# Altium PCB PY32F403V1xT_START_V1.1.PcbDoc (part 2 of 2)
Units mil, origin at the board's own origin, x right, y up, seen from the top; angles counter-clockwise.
Board outline 1771.65 x 2660.63 mil, 2 copper layers (Top Layer, Bottom Layer); 52 components, 105 nets, 324 pads, 111 vias.
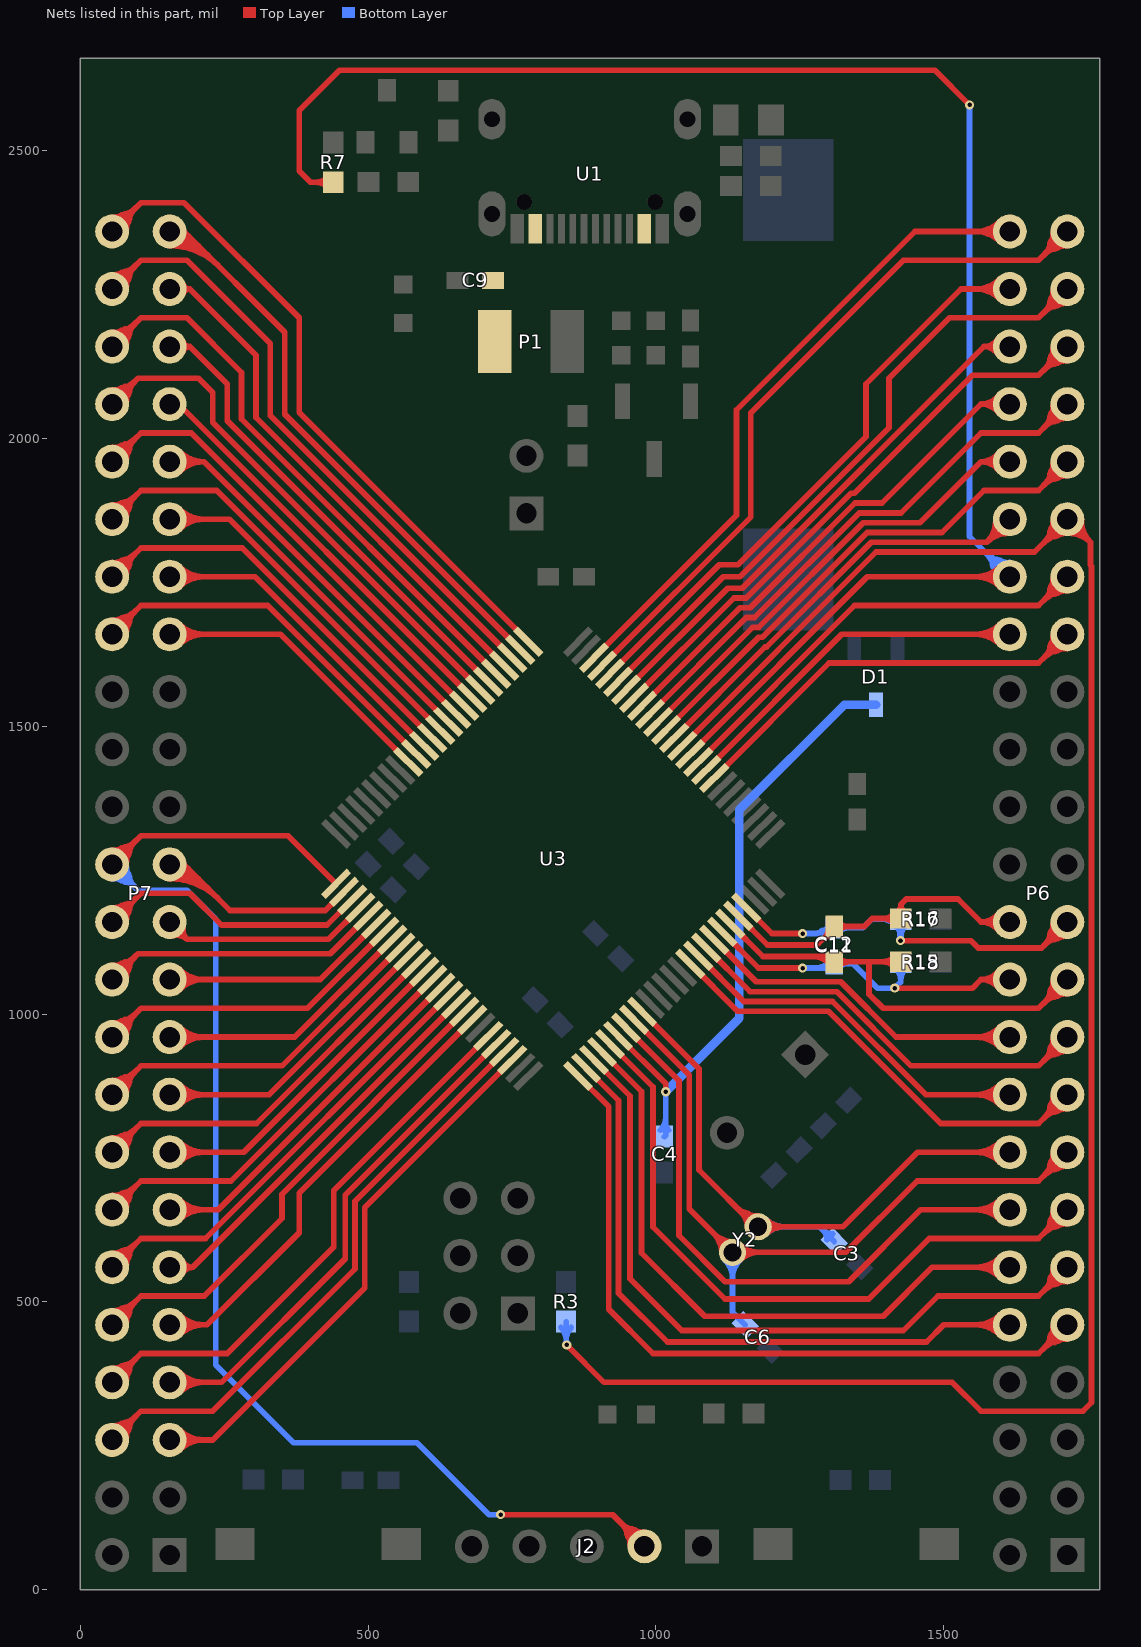
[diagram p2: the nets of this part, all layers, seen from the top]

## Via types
v1: diameter 15.75, hole 7.87, Top Layer to Bottom Layer, 109 vias
v2: diameter 65, hole 44, Top Layer to Bottom Layer, 1 vias
v3: diameter 55, hole 34, Top Layer to Bottom Layer, 1 vias

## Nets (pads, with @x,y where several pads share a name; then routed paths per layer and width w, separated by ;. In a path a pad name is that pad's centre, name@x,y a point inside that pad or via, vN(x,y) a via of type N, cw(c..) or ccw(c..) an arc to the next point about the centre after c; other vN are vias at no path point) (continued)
PA14: J2.2 P7.26 U3.76 | length 3457.4
  Top Layer w10: P7.26@49.64,1261.1 cw(c87.3,1253.39) 77.35,1290.52 ; P7.26@55,1260 105,1310 360.87,1310 U3.76@444.26,1226.61 ; P7.26@56.1,1254.64 ccw(c48.39,1292.3) 85.52,1282.35 ; 79.8,1284.8 cw(c55,1309.6) 55,1274.53 ccw(c55,1309.6) 79.8,1284.8 ; 79.8,1284.8 ccw(c104.6,1260) 69.53,1260 cw(c104.6,1260) 79.8,1284.8 ; 96.87,1301.87 cw(c55,1343.74) 55,1284.53 ccw(c55,1343.74) 96.87,1301.87 ; 96.87,1301.87 ccw(c138.74,1260) 79.53,1260 cw(c138.74,1260) 96.87,1301.87
  Top Layer w10.02: v1(730,130) 925,130 J2.2@980,75 ; 949.53,97.23 ccw(c986.59,107.16) J2.2@978.89,69.57 ; 957.77,105.47 cw(c947.84,68.41) J2.2@985.43,76.11 ; 938.15,116.85 cw(c896.29,75) 955.48,75 ccw(c896.29,75) 938.15,116.85 ; 938.15,116.85 ccw(c980,158.71) 980,99.52 cw(c980,158.71) 938.15,116.85 ; 955.25,99.75 cw(c930.5,75) 965.5,75 ccw(c930.5,75) 955.25,99.75 ; 955.25,99.75 ccw(c980,124.5) 980,89.5 cw(c980,124.5) 955.25,99.75
  Bottom Layer w10.02: P7.26@49.57,1258.89 ccw(c87.16,1266.59) 77.23,1229.53 ; P7.26@55,1260 100,1215 185,1215 235,1165 235,390 370,255 585,255 710,130 v1(730,130) ; P7.26@56.11,1265.43 cw(c48.41,1227.84) 85.47,1237.77 ; 79.75,1235.25 cw(c104.5,1260) 69.5,1260 ccw(c104.5,1260) 79.75,1235.25 ; 79.75,1235.25 ccw(c55,1210.5) 55,1245.5 cw(c55,1210.5) 79.75,1235.25 ; 96.85,1218.15 cw(c138.71,1260) 79.52,1260 ccw(c138.71,1260) 96.85,1218.15 ; 96.85,1218.15 ccw(c55,1176.29) 55,1235.48 cw(c55,1176.29) 96.85,1218.15
PA15: P7.25 U3.77 | length 625.9
  Top Layer w10: P7.25@155,1235.47 cw(c155,1115.9) 239.55,1200.45 ; P7.25@155,1245.47 cw(c155,1150.04) 222.48,1217.52 ; P7.25@155,1255.47 cw(c155,1184.19) 205.41,1234.59 ; P7.25@155,1265.47 cw(c155,1218.33) 188.34,1251.66 ; P7.25@165,1250 P7.25@155,1260 180,1260 260,1180 425.49,1180 U3.77@458.18,1212.69
PB0: P6.35 U3.35 | length 1155.7
  Top Layer w10.02: U3.35@1073.42,1438.18 1345.24,1710 1665,1710 P6.35@1715,1760 ; 1684.53,1737.77 cw(c1721.59,1727.84) P6.35@1713.89,1765.43 ; 1692.77,1729.53 ccw(c1682.84,1766.59) P6.35@1720.43,1758.89 ; 1673.15,1718.15 cw(c1715,1676.29) 1715,1735.48 ccw(c1715,1676.29) 1673.15,1718.15 ; 1673.15,1718.15 ccw(c1631.29,1760) 1690.48,1760 cw(c1631.29,1760) 1673.15,1718.15 ; 1690.25,1735.25 cw(c1715,1710.5) 1715,1745.5 ccw(c1715,1710.5) 1690.25,1735.25 ; 1690.25,1735.25 ccw(c1665.5,1760) 1700.5,1760 cw(c1665.5,1760) 1690.25,1735.25
PB1: P6.36 R7.1 U3.36 | length 3695.2
  Top Layer w10: R7.1@439.2,2445.5 399.5,2445.5 380,2465 380,2570 450,2640 1485,2640 v1(1545,2580) ; 409.02,2445.5 cw(c409.02,2415.32) 430.36,2436.66 ccw(c409.02,2415.32) 409.02,2445.5 ; 409.02,2445.5 ccw(c409.02,2475.68) 430.36,2454.34 cw(c409.02,2475.68) 409.02,2445.5
  Top Layer w10.02: U3.36@1059.5,1452.1 1367.4,1760 P6.36@1615,1760 ; 1555.81,1760 cw(c1555.81,1700.81) 1597.66,1742.66 ccw(c1555.81,1700.81) 1555.81,1760 ; 1555.81,1760 ccw(c1555.81,1819.19) 1597.66,1777.34 cw(c1555.81,1819.19) 1555.81,1760 ; 1580,1760 cw(c1580,1725) 1604.75,1749.75 ccw(c1580,1725) 1580,1760 ; 1580,1760 ccw(c1580,1795) 1604.75,1770.25 cw(c1580,1795) 1580,1760
  Bottom Layer w10: v1(1545,2580) 1545,1830 P6.36@1615,1760 ; 1584.48,1782.35 ccw(c1621.61,1792.3) P6.36@1613.9,1754.64 ; 1592.65,1790.52 cw(c1582.7,1753.39) P6.36@1620.36,1761.1 ; 1573.13,1801.87 cw(c1531.26,1760) 1590.47,1760 ccw(c1531.26,1760) 1573.13,1801.87 ; 1573.13,1801.87 ccw(c1615,1843.74) 1615,1784.53 cw(c1615,1843.74) 1573.13,1801.87 ; 1590.2,1784.8 cw(c1565.4,1760) 1600.47,1760 ccw(c1565.4,1760) 1590.2,1784.8 ; 1590.2,1784.8 ccw(c1615,1809.6) 1615,1774.53 cw(c1615,1809.6) 1590.2,1784.8
PB2: P6.37 R3.2 U3.37 | length 4021.9
  Top Layer w10: v1(845,425) 910,360 1515,360 1565,310 1742.15,310 1757.15,325 1757.15,1778.1 1755,1780.26 1755,1820 ; P6.37@1715,1860 1755,1820 ; P6.37@1715.48,1845.48 cw(c1716.51,1814.13) 1738.69,1836.31 cw(c1760.87,1858.49) P6.37@1729.52,1859.52 ; P6.37@1715.81,1835.49 cw(c1717.55,1782.55) 1755,1820 ; P6.37@1739.51,1859.19 ccw(c1792.45,1857.45) 1755,1820
  Top Layer w10.02: U3.37@1045.57,1466.02 1382.43,1802.88 1657.88,1802.88 P6.37@1715,1860 ; 1684.53,1837.77 cw(c1721.59,1827.84) P6.37@1713.89,1865.43 ; 1692.77,1829.53 ccw(c1682.84,1866.59) P6.37@1720.43,1858.89 ; 1673.15,1818.15 cw(c1715,1776.29) 1715,1835.48 ccw(c1715,1776.29) 1673.15,1818.15 ; 1673.15,1818.15 ccw(c1631.29,1860) 1690.48,1860 cw(c1631.29,1860) 1673.15,1818.15 ; 1690.25,1835.25 cw(c1715,1810.5) 1715,1845.5 ccw(c1715,1810.5) 1690.25,1835.25 ; 1690.25,1835.25 ccw(c1665.5,1860) 1700.5,1860 cw(c1665.5,1860) 1690.25,1835.25
  Bottom Layer w10: R3.2@844,465.5 844,426 v1(845,425) ; 844,433.82 cw(c874.18,433.82) 852.84,455.16 ccw(c874.18,433.82) 844,433.82 ; 844,433.82 ccw(c813.82,433.82) 835.16,455.16 cw(c813.82,433.82) 844,433.82 ; 844,434.35 ccw(c854.35,434.35) 847.03,427.03 cw(c854.35,434.35) 844,434.35
PB3: P7.13 U3.89 | length 926.2
  Top Layer w10: P7.13@155,660 239.55,660 U3.89@625.21,1045.66 ; 190.07,660 cw(c190.07,695.07) 165.27,670.27 ccw(c190.07,695.07) 190.07,660 ; 190.07,660 ccw(c190.07,624.93) 165.27,649.73 cw(c190.07,624.93) 190.07,660 ; 214.21,660 cw(c214.21,719.21) 172.34,677.34 ccw(c214.21,719.21) 214.21,660 ; 214.21,660 ccw(c214.21,600.79) 172.34,642.66 cw(c214.21,600.79) 214.21,660
PB4: P7.12 U3.90 | length 1160.9
  Top Layer w10: P7.12@49.64,561.1 cw(c87.3,553.39) 77.35,590.52 ; P7.12@55,560 105,610 217.4,610 U3.90@639.14,1031.74 ; P7.12@56.1,554.64 ccw(c48.39,592.3) 85.52,582.35 ; 79.8,584.8 cw(c55,609.6) 55,574.53 ccw(c55,609.6) 79.8,584.8 ; 79.8,584.8 ccw(c104.6,560) 69.53,560 cw(c104.6,560) 79.8,584.8 ; 96.87,601.87 cw(c55,643.74) 55,584.53 ccw(c55,643.74) 96.87,601.87 ; 96.87,601.87 ccw(c138.74,560) 79.53,560 cw(c138.74,560) 96.87,601.87
PB5: P7.11 U3.91 | length 778.5
  Top Layer w10: P7.11@155,560 195.24,560 ; U3.91@653.06,1017.82 195.24,560 ; 195.24,560 cw(c195.24,580.75) 176.8,571.24 ccw(c195.24,580.75) 195.24,560 ; 195.24,560 ccw(c195.24,539.25) 176.8,548.76 cw(c195.24,539.25) 195.24,560
PB6: P7.10 U3.92 | length 1243.1
  Top Layer w10: P7.10@49.64,461.1 cw(c87.3,453.39) 77.35,490.52 ; P7.10@55,460 105,510 215,510 350,645 350,686.92 U3.92@666.97,1003.9 ; P7.10@56.1,454.64 ccw(c48.39,492.3) 85.52,482.35 ; 79.8,484.8 cw(c55,509.6) 55,474.53 ccw(c55,509.6) 79.8,484.8 ; 79.8,484.8 ccw(c104.6,460) 69.53,460 cw(c104.6,460) 79.8,484.8 ; 96.87,501.87 cw(c55,543.74) 55,484.53 ccw(c55,543.74) 96.87,501.87 ; 96.87,501.87 ccw(c138.74,460) 79.53,460 cw(c138.74,460) 96.87,501.87
PB7: P7.9 U3.93 | length 1082.1
  Top Layer w10: P7.9@155,460 220,460 380,620 380,689.08 U3.93@680.9,989.98 ; 190.07,460 cw(c190.07,495.07) 165.27,470.27 ccw(c190.07,495.07) 190.07,460 ; 190.07,460 ccw(c190.07,424.93) 165.27,449.73 cw(c190.07,424.93) 190.07,460 ; 214.21,460 cw(c214.21,519.21) 172.34,477.34 ccw(c214.21,519.21) 214.21,460 ; 214.21,460 ccw(c214.21,400.79) 172.34,442.66 cw(c214.21,400.79) 214.21,460
PB8: P7.8 U3.95 | length 1342.1
  Top Layer w10: P7.8@49.64,361.1 cw(c87.3,353.39) 77.35,390.52 ; P7.8@55,360 105,410 255,410 440,595 440,693.4 U3.95@708.74,962.14 ; P7.8@56.1,354.64 ccw(c48.39,392.3) 85.52,382.35 ; 79.8,384.8 cw(c55,409.6) 55,374.53 ccw(c55,409.6) 79.8,384.8 ; 79.8,384.8 ccw(c104.6,360) 69.53,360 cw(c104.6,360) 79.8,384.8 ; 96.87,401.87 cw(c55,443.74) 55,384.53 ccw(c55,443.74) 96.87,401.87 ; 96.87,401.87 ccw(c138.74,360) 79.53,360 cw(c138.74,360) 96.87,401.87
PB9: P7.7 U3.96 | length 1172.3
  Top Layer w10: P7.7@155,360 245,360 460,575 460,685.57 U3.96@722.65,948.22 ; 190.07,360 cw(c190.07,395.07) 165.27,370.27 ccw(c190.07,395.07) 190.07,360 ; 190.07,360 ccw(c190.07,324.93) 165.27,349.73 cw(c190.07,324.93) 190.07,360 ; 214.21,360 cw(c214.21,419.21) 172.34,377.34 ccw(c214.21,419.21) 214.21,360 ; 214.21,360 ccw(c214.21,300.79) 172.34,342.66 cw(c214.21,300.79) 214.21,360
PB10: P6.47 U3.47 | length 1608.7
  Top Layer w10: U3.47@906.38,1605.22 1165,1863.84 1165,2045 1430,2310 1665,2310 P6.47@1715,2360 ; 1684.48,2337.65 cw(c1721.61,2327.7) P6.47@1713.9,2365.36 ; 1692.65,2329.48 ccw(c1682.7,2366.61) P6.47@1720.36,2358.9 ; 1673.13,2318.13 cw(c1715,2276.26) 1715,2335.47 ccw(c1715,2276.26) 1673.13,2318.13 ; 1673.13,2318.13 ccw(c1631.26,2360) 1690.47,2360 cw(c1631.26,2360) 1673.13,2318.13 ; 1690.2,2335.2 cw(c1715,2310.4) 1715,2345.47 ccw(c1715,2310.4) 1690.2,2335.2 ; 1690.2,2335.2 ccw(c1665.4,2360) 1700.47,2360 cw(c1665.4,2360) 1690.2,2335.2
PB11: P6.48 U3.48 | length 1433
  Top Layer w10: U3.48@892.46,1619.13 1140,1866.67 1140,2050 1450,2360 P6.48@1615,2360 ; 1555.79,2360 cw(c1555.79,2300.79) 1597.66,2342.66 ccw(c1555.79,2300.79) 1555.79,2360 ; 1555.79,2360 ccw(c1555.79,2419.21) 1597.66,2377.34 cw(c1555.79,2419.21) 1555.79,2360 ; 1579.93,2360 cw(c1579.93,2324.93) 1604.73,2349.73 ccw(c1579.93,2324.93) 1579.93,2360 ; 1579.93,2360 ccw(c1579.93,2395.07) 1604.73,2370.27 cw(c1579.93,2395.07) 1579.93,2360
PB12: P7.48 U3.51 | length 1537.9
  Top Layer w10: P7.48@49.64,2361.1 cw(c87.3,2353.39) 77.35,2390.52 ; P7.48@55,2360 105,2410 180,2410 380,2210 380,2045.3 U3.51@778.33,1646.97 ; P7.48@56.1,2354.64 ccw(c48.39,2392.3) 85.52,2382.35 ; 79.8,2384.8 cw(c55,2409.6) 55,2374.53 ccw(c55,2409.6) 79.8,2384.8 ; 79.8,2384.8 ccw(c104.6,2360) 69.53,2360 cw(c104.6,2360) 79.8,2384.8 ; 96.87,2401.87 cw(c55,2443.74) 55,2384.53 ccw(c55,2443.74) 96.87,2401.87 ; 96.87,2401.87 ccw(c138.74,2360) 79.53,2360 cw(c138.74,2360) 96.87,2401.87
PB13: P7.47 U3.52 | length 1255.9
  Top Layer w10: P7.47@155,2335.47 cw(c155,2215.9) 239.55,2300.45 ; P7.47@155,2345.47 cw(c155,2250.04) 222.48,2317.52 ; P7.47@155,2355.47 cw(c155,2284.19) 205.41,2334.59 ; P7.47@155,2360 180,2360 355,2185 355,2042.47 U3.52@764.41,1633.05 ; P7.47@155,2365.47 cw(c155,2318.33) 188.34,2351.66
PB14: P7.46 U3.53 | length 1457.1
  Top Layer w10: P7.46@49.64,2261.1 cw(c87.3,2253.39) 77.35,2290.52 ; P7.46@55,2260 105,2310 185,2310 330,2165 330,2039.62 U3.53@750.49,1619.13 ; P7.46@56.1,2254.64 ccw(c48.39,2292.3) 85.52,2282.35 ; 79.8,2284.8 cw(c55,2309.6) 55,2274.53 ccw(c55,2309.6) 79.8,2284.8 ; 79.8,2284.8 ccw(c104.6,2260) 69.53,2260 cw(c104.6,2260) 79.8,2284.8 ; 96.87,2301.87 cw(c55,2343.74) 55,2284.53 ccw(c55,2343.74) 96.87,2301.87 ; 96.87,2301.87 ccw(c138.74,2260) 79.53,2260 cw(c138.74,2260) 96.87,2301.87
PB15: P7.45 U3.54 | length 978.3
  Top Layer w10: P7.45@155,2260 190,2260 ; U3.54@736.57,1605.22 305,2036.79 305,2145 190,2260 ; 190,2260 cw(c190,2272.71) 178.06,2268.37 ccw(c190,2272.71) 190,2260 ; 190,2260 ccw(c190,2247.29) 178.06,2251.63 cw(c190,2247.29) 190,2260
PC0: P6.17 U3.15 | length 1172.4
  Top Layer w10: U3.15@1059.5,1087.42 1141.91,1005 1300,1005 1495,810 1665,810 P6.17@1715,860 ; 1684.48,837.65 cw(c1721.61,827.7) P6.17@1713.9,865.36 ; 1692.65,829.48 ccw(c1682.7,866.61) P6.17@1720.36,858.9 ; 1673.13,818.13 cw(c1715,776.26) 1715,835.47 ccw(c1715,776.26) 1673.13,818.13 ; 1673.13,818.13 ccw(c1631.26,860) 1690.47,860 cw(c1631.26,860) 1673.13,818.13 ; 1690.2,835.2 cw(c1715,810.4) 1715,845.47 ccw(c1715,810.4) 1690.2,835.2 ; 1690.2,835.2 ccw(c1665.4,860) 1700.47,860 cw(c1665.4,860) 1690.2,835.2
PC1: P6.18 U3.16 | length 937.8
  Top Layer w10: U3.16@1073.42,1101.34 1152.76,1022 1307.04,1022 1469.04,860 P6.18@1615,860 ; 1555.79,860 cw(c1555.79,800.79) 1597.66,842.66 ccw(c1555.79,800.79) 1555.79,860 ; 1555.79,860 ccw(c1555.79,919.21) 1597.66,877.34 cw(c1555.79,919.21) 1555.79,860 ; 1579.93,860 cw(c1579.93,824.93) 1604.73,849.73 ccw(c1579.93,824.93) 1579.93,860 ; 1579.93,860 ccw(c1579.93,895.07) 1604.73,870.27 cw(c1579.93,895.07) 1579.93,860
PC2: P6.19 U3.17 | length 1114.7
  Top Layer w10: U3.17@1087.34,1115.25 1163.59,1039 1314.08,1039 1443.08,910 1665,910 P6.19@1715,960 ; 1684.48,937.65 cw(c1721.61,927.7) P6.19@1713.9,965.36 ; 1692.65,929.48 ccw(c1682.7,966.61) P6.19@1720.36,958.9 ; 1673.13,918.13 cw(c1715,876.26) 1715,935.47 ccw(c1715,876.26) 1673.13,918.13 ; 1673.13,918.13 ccw(c1631.26,960) 1690.47,960 cw(c1631.26,960) 1673.13,918.13 ; 1690.2,935.2 cw(c1715,910.4) 1715,945.47 ccw(c1715,910.4) 1690.2,935.2 ; 1690.2,935.2 ccw(c1665.4,960) 1700.47,960 cw(c1665.4,960) 1690.2,935.2
PC3: P6.20 U3.18 | length 880
  Top Layer w10: U3.18@1101.26,1129.18 1174.44,1056 1321.12,1056 1417.12,960 P6.20@1615,960 ; 1555.79,960 cw(c1555.79,900.79) 1597.66,942.66 ccw(c1555.79,900.79) 1555.79,960 ; 1555.79,960 ccw(c1555.79,1019.21) 1597.66,977.34 cw(c1555.79,1019.21) 1555.79,960 ; 1579.93,960 cw(c1579.93,924.93) 1604.73,949.73 ccw(c1579.93,924.93) 1579.93,960 ; 1579.93,960 ccw(c1579.93,995.07) 1604.73,970.27 cw(c1579.93,995.07) 1579.93,960
PC4: P6.33 U3.33 | length 1098
  Top Layer w10.02: U3.33@1101.26,1410.34 1300.92,1610 1665,1610 P6.33@1715,1660 ; 1684.53,1637.77 cw(c1721.59,1627.84) P6.33@1713.89,1665.43 ; 1692.77,1629.53 ccw(c1682.84,1666.59) P6.33@1720.43,1658.89 ; 1673.15,1618.15 cw(c1715,1576.29) 1715,1635.48 ccw(c1715,1576.29) 1673.15,1618.15 ; 1673.15,1618.15 ccw(c1631.29,1660) 1690.48,1660 cw(c1631.29,1660) 1673.15,1618.15 ; 1690.25,1635.25 cw(c1715,1610.5) 1715,1645.5 ccw(c1715,1610.5) 1690.25,1635.25 ; 1690.25,1635.25 ccw(c1665.5,1660) 1700.5,1660 cw(c1665.5,1660) 1690.25,1635.25
PC5: P6.34 U3.34 | length 921.2
  Top Layer w10.02: U3.34@1087.34,1424.26 1323.08,1660 P6.34@1615,1660 ; 1555.81,1660 cw(c1555.81,1600.81) 1597.66,1642.66 ccw(c1555.81,1600.81) 1555.81,1660 ; 1555.81,1660 ccw(c1555.81,1719.19) 1597.66,1677.34 cw(c1555.81,1719.19) 1555.81,1660 ; 1580,1660 cw(c1580,1625) 1604.75,1649.75 ccw(c1580,1625) 1580,1660 ; 1580,1660 ccw(c1580,1695) 1604.75,1670.25 cw(c1580,1695) 1580,1660
PC6: P7.36 U3.63 | length 1110
  Top Layer w10: P7.36@49.64,1761.1 cw(c87.3,1753.39) 77.35,1790.52 ; P7.36@55,1745 P7.36@55,1760 105,1810 281.23,1810 U3.63@611.3,1479.94 ; P7.36@56.1,1754.64 ccw(c48.39,1792.3) 85.52,1782.35 ; 79.8,1784.8 cw(c55,1809.6) 55,1774.53 ccw(c55,1809.6) 79.8,1784.8 ; 79.8,1784.8 ccw(c104.6,1760) 69.53,1760 cw(c104.6,1760) 79.8,1784.8 ; 96.87,1801.87 cw(c55,1843.74) 55,1784.53 ccw(c55,1843.74) 96.87,1801.87 ; 96.87,1801.87 ccw(c138.74,1760) 79.53,1760 cw(c138.74,1760) 96.87,1801.87
PC7: P7.35 U3.64 | length 860.4
  Top Layer w10: P7.35@155,1760 303.4,1760 U3.64@597.38,1466.02 ; 190.07,1760 cw(c190.07,1795.07) 165.27,1770.27 ccw(c190.07,1795.07) 190.07,1760 ; 190.07,1760 ccw(c190.07,1724.93) 165.27,1749.73 cw(c190.07,1724.93) 190.07,1760 ; 214.21,1760 cw(c214.21,1819.21) 172.34,1777.34 ccw(c214.21,1819.21) 214.21,1760 ; 214.21,1760 ccw(c214.21,1700.79) 172.34,1742.66 cw(c214.21,1700.79) 214.21,1760
PC8: P7.34 U3.65 | length 1037.3
  Top Layer w10: P7.34@49.64,1661.1 cw(c87.3,1653.39) 77.35,1690.52 ; P7.34@55,1660 105,1710 325.56,1710 U3.65@583.46,1452.1 ; P7.34@56.1,1654.64 ccw(c48.39,1692.3) 85.52,1682.35 ; 79.8,1684.8 cw(c55,1709.6) 55,1674.53 ccw(c55,1709.6) 79.8,1684.8 ; 79.8,1684.8 ccw(c104.6,1660) 69.53,1660 cw(c104.6,1660) 79.8,1684.8 ; 96.87,1701.87 cw(c55,1743.74) 55,1684.53 ccw(c55,1743.74) 96.87,1701.87 ; 96.87,1701.87 ccw(c138.74,1660) 79.53,1660 cw(c138.74,1660) 96.87,1701.87
PC9: P7.33 U3.66 | length 802.6
  Top Layer w10: P7.33@155,1660 347.71,1660 U3.66@569.54,1438.18 ; 190.07,1660 cw(c190.07,1695.07) 165.27,1670.27 ccw(c190.07,1695.07) 190.07,1660 ; 190.07,1660 ccw(c190.07,1624.93) 165.27,1649.73 cw(c190.07,1624.93) 190.07,1660 ; 214.21,1660 cw(c214.21,1719.21) 172.34,1677.34 ccw(c214.21,1719.21) 214.21,1660 ; 214.21,1660 ccw(c214.21,1600.79) 172.34,1642.66 cw(c214.21,1600.79) 214.21,1660
PC10: P7.24 U3.78 | length 860
  Top Layer w10: P7.24@49.64,1161.1 cw(c87.3,1153.39) 77.35,1190.52 ; P7.24@55,1160 105,1210 190,1210 245,1155 428.33,1155 U3.78@472.1,1198.77 ; P7.24@56.1,1154.64 ccw(c48.39,1192.3) 85.52,1182.35 ; 79.8,1184.8 cw(c55,1209.6) 55,1174.53 ccw(c55,1209.6) 79.8,1184.8 ; 79.8,1184.8 ccw(c104.6,1160) 69.53,1160 cw(c104.6,1160) 79.8,1184.8 ; 96.87,1201.87 cw(c55,1243.74) 55,1184.53 ccw(c55,1243.74) 96.87,1201.87 ; 96.87,1201.87 ccw(c138.74,1160) 79.53,1160 cw(c138.74,1160) 96.87,1201.87
PC11: P7.23 U3.79 | length 537
  Top Layer w10: P7.23@144.07,1149.05 ccw(c174.82,1179.87) 174.87,1136.33 ; P7.23@155,1160 185,1130 ; P7.23@165.95,1170.93 cw(c135.13,1140.18) 178.67,1140.13 ; U3.79@486.02,1184.86 431.16,1130 185,1130 ; 185,1130 cw(c202.27,1147.27) 178.68,1153.62 ccw(c202.27,1147.27) 185,1130 ; 185,1130 ccw(c167.73,1112.73) 161.38,1136.32 cw(c167.73,1112.73) 185,1130
PC12: P7.22 U3.80 | length 872.2
  Top Layer w10: P7.22@49.64,1061.1 cw(c87.3,1053.39) 77.35,1090.52 ; P7.22@55,1060 100,1105 434.01,1105 U3.80@499.94,1170.93 ; P7.22@56.1,1054.64 ccw(c48.39,1092.3) 85.52,1082.35 ; 79.8,1084.8 cw(c55,1109.6) 55,1074.53 ccw(c55,1109.6) 79.8,1084.8 ; 79.8,1084.8 ccw(c104.6,1060) 69.53,1060 cw(c104.6,1060) 79.8,1084.8 ; 96.87,1101.87 cw(c55,1143.74) 55,1084.53 ccw(c55,1143.74) 96.87,1101.87 ; 96.87,1101.87 ccw(c138.74,1060) 79.53,1060 cw(c138.74,1060) 96.87,1101.87
PC13: P6.14 U3.7 | length 1355.2
  Top Layer w10: U3.7@948.14,976.06 1040,884.2 1040,615 1120,535 1335,535 1460,660 P6.14@1615,660 ; 1555.79,660 cw(c1555.79,600.79) 1597.66,642.66 ccw(c1555.79,600.79) 1555.79,660 ; 1555.79,660 ccw(c1555.79,719.21) 1597.66,677.34 cw(c1555.79,719.21) 1555.79,660 ; 1579.93,660 cw(c1579.93,624.93) 1604.73,649.73 ccw(c1579.93,624.93) 1579.93,660 ; 1579.93,660 ccw(c1579.93,695.07) 1604.73,670.27 cw(c1579.93,695.07) 1579.93,660
PC14: C6.1 P6.15 U3.8 Y2.2 | length 2137.7
  Top Layer w10.02: U3.8@962.06,989.98 1057.89,894.14 1057.89,661.15 Y2.2@1133.12,585.92 1330,585.92 1454.08,710 1665,710 P6.15@1715,760 ; 1108.82,607.14 ccw(c1139.13,615.26) Y2.2@1132.84,584.52 ; 1111.9,610.21 cw(c1103.78,579.91) Y2.2@1134.52,586.2 ; 1684.53,737.77 cw(c1721.59,727.84) P6.15@1713.89,765.43 ; 1692.77,729.53 ccw(c1682.84,766.59) P6.15@1720.43,758.89 ; 1101.35,617.69 cw(c1069.58,585.92) 1114.51,585.92 ccw(c1069.58,585.92) 1101.35,617.69 ; 1101.35,617.69 ccw(c1133.12,649.46) 1133.12,604.53 cw(c1133.12,649.46) 1101.35,617.69 ; 1178.06,585.92 cw(c1178.06,630.85) 1146.28,599.08 ccw(c1178.06,630.85) 1178.06,585.92 ; 1178.06,585.92 ccw(c1178.06,540.98) 1146.28,572.76 cw(c1178.06,540.98) 1178.06,585.92 ; 1673.15,718.15 cw(c1715,676.29) 1715,735.48 ccw(c1715,676.29) 1673.15,718.15 ; 1673.15,718.15 ccw(c1631.29,760) 1690.48,760 cw(c1631.29,760) 1673.15,718.15 ; 1690.25,735.25 cw(c1715,710.5) 1715,745.5 ccw(c1715,710.5) 1690.25,735.25 ; 1690.25,735.25 ccw(c1665.5,760) 1700.5,760 cw(c1665.5,760) 1690.25,735.25
  Bottom Layer w10.02: Y2.2@1133.12,585.92 1133.12,481.88 C6.1@1155,460 ; 1133.12,540.98 cw(c1178.06,540.98) 1146.28,572.76 ccw(c1178.06,540.98) 1133.12,540.98 ; 1133.12,540.98 ccw(c1088.19,540.98) 1119.96,572.76 cw(c1088.19,540.98) 1133.12,540.98
PC15: C3.1 P6.16 U3.9 Y2.1 | length 2006.1
  Top Layer w10.02: U3.9@975.98,1003.9 1075,904.88 1075,729.02 1173.56,630.46 Y2.1@1177.66,630.46 1325,630.46 1454.54,760 P6.16@1615,760 ; 1153.97,649.44 ccw(c1180.8,656.63) Y2.1@1177.49,629.04 ; 1154.21,655.36 cw(c1145.07,621.27) Y2.1@1179.04,630.85 ; 1222.6,630.46 cw(c1222.6,675.39) 1190.83,643.62 ccw(c1222.6,675.39) 1222.6,630.46 ; 1222.6,630.46 ccw(c1222.6,585.53) 1190.83,617.3 cw(c1222.6,585.53) 1222.6,630.46 ; 1555.81,760 cw(c1555.81,700.81) 1597.66,742.66 ccw(c1555.81,700.81) 1555.81,760 ; 1555.81,760 ccw(c1555.81,819.19) 1597.66,777.34 cw(c1555.81,819.19) 1555.81,760 ; 1580,760 cw(c1580,725) 1604.75,749.75 ccw(c1580,725) 1580,760 ; 1580,760 ccw(c1580,795) 1604.75,770.25 cw(c1580,795) 1580,760 ; 1138.89,665.13 ccw(c1177.66,703.91) 1177.66,649.07 cw(c1177.66,703.91) 1138.89,665.13 ; 1148.79,655.23 cw(c1124.02,630.46) 1159.05,630.46 ccw(c1124.02,630.46) 1148.79,655.23 ; 1155.99,648.03 ccw(c1177.66,669.7) 1177.66,639.05 cw(c1177.66,669.7) 1155.99,648.03
  Bottom Layer w10.02: Y2.1@1177.66,630.46 1284.54,630.46 C3.1@1310,605 ; 1222.6,630.46 cw(c1222.6,675.39) 1190.83,643.62 ccw(c1222.6,675.39) 1222.6,630.46 ; 1222.6,630.46 ccw(c1222.6,585.53) 1190.83,617.3 cw(c1222.6,585.53) 1222.6,630.46 ; 1290.12,624.88 cw(c1273.06,607.83) 1297.18,607.83 ccw(c1273.06,607.83) 1290.12,624.88 ; 1290.12,624.88 ccw(c1307.17,641.94) 1307.17,617.82 cw(c1307.17,641.94) 1290.12,624.88
PD0: P7.21 U3.81 | length 695.3
  Top Layer w10: P7.21@155,1060 416.84,1060 U3.81@513.86,1157.02 ; 190.07,1060 cw(c190.07,1095.07) 165.27,1070.27 ccw(c190.07,1095.07) 190.07,1060 ; 190.07,1060 ccw(c190.07,1024.93) 165.27,1049.73 cw(c190.07,1024.93) 190.07,1060 ; 214.21,1060 cw(c214.21,1119.21) 172.34,1077.34 ccw(c214.21,1119.21) 214.21,1060 ; 214.21,1060 ccw(c214.21,1000.79) 172.34,1042.66 cw(c214.21,1000.79) 214.21,1060
PD1: P7.20 U3.82 | length 929.9
  Top Layer w10: P7.20@49.64,961.1 cw(c87.3,953.39) 77.35,990.52 ; P7.20@55,960 105,1010 394.69,1010 U3.82@527.78,1143.09 ; P7.20@56.1,954.64 ccw(c48.39,992.3) 85.52,982.35 ; 79.8,984.8 cw(c55,1009.6) 55,974.53 ccw(c55,1009.6) 79.8,984.8 ; 79.8,984.8 ccw(c104.6,960) 69.53,960 cw(c104.6,960) 79.8,984.8 ; 96.87,1001.87 cw(c55,1043.74) 55,984.53 ccw(c55,1043.74) 96.87,1001.87 ; 96.87,1001.87 ccw(c138.74,960) 79.53,960 cw(c138.74,960) 96.87,1001.87
PD2: P7.19 U3.83 | length 753
  Top Layer w10: P7.19@155,960 372.52,960 U3.83@541.7,1129.18 ; 190.07,960 cw(c190.07,995.07) 165.27,970.27 ccw(c190.07,995.07) 190.07,960 ; 190.07,960 ccw(c190.07,924.93) 165.27,949.73 cw(c190.07,924.93) 190.07,960 ; 214.21,960 cw(c214.21,1019.21) 172.34,977.34 ccw(c214.21,1019.21) 214.21,960 ; 214.21,960 ccw(c214.21,900.79) 172.34,942.66 cw(c214.21,900.79) 214.21,960
PD3: P7.18 U3.84 | length 987.7
  Top Layer w10: P7.18@49.64,861.1 cw(c87.3,853.39) 77.35,890.52 ; P7.18@55,860 105,910 350.36,910 U3.84@555.62,1115.25 ; P7.18@56.1,854.64 ccw(c48.39,892.3) 85.52,882.35 ; 79.8,884.8 cw(c55,909.6) 55,874.53 ccw(c55,909.6) 79.8,884.8 ; 79.8,884.8 ccw(c104.6,860) 69.53,860 cw(c104.6,860) 79.8,884.8 ; 96.87,901.87 cw(c55,943.74) 55,884.53 ccw(c55,943.74) 96.87,901.87 ; 96.87,901.87 ccw(c138.74,860) 79.53,860 cw(c138.74,860) 96.87,901.87
PD4: P7.17 U3.85 | length 810.7
  Top Layer w10: P7.17@155,860 328.2,860 U3.85@569.54,1101.34 ; 190.07,860 cw(c190.07,895.07) 165.27,870.27 ccw(c190.07,895.07) 190.07,860 ; 190.07,860 ccw(c190.07,824.93) 165.27,849.73 cw(c190.07,824.93) 190.07,860 ; 214.21,860 cw(c214.21,919.21) 172.34,877.34 ccw(c214.21,919.21) 214.21,860 ; 214.21,860 ccw(c214.21,800.79) 172.34,842.66 cw(c214.21,800.79) 214.21,860
PD5: P7.16 U3.86 | length 1045.4
  Top Layer w10: P7.16@49.64,761.1 cw(c87.3,753.39) 77.35,790.52 ; P7.16@55,760 105,810 306.04,810 U3.86@583.46,1087.42 ; P7.16@56.1,754.64 ccw(c48.39,792.3) 85.52,782.35 ; 79.8,784.8 cw(c55,809.6) 55,774.53 ccw(c55,809.6) 79.8,784.8 ; 79.8,784.8 ccw(c104.6,760) 69.53,760 cw(c104.6,760) 79.8,784.8 ; 96.87,801.87 cw(c55,843.74) 55,784.53 ccw(c55,843.74) 96.87,801.87 ; 96.87,801.87 ccw(c138.74,760) 79.53,760 cw(c138.74,760) 96.87,801.87
PD6: P7.15 U3.87 | length 868.4
  Top Layer w10: P7.15@155,760 283.87,760 U3.87@597.37,1073.5 ; 190.07,760 cw(c190.07,795.07) 165.27,770.27 ccw(c190.07,795.07) 190.07,760 ; 190.07,760 ccw(c190.07,724.93) 165.27,749.73 cw(c190.07,724.93) 190.07,760 ; 214.21,760 cw(c214.21,819.21) 172.34,777.34 ccw(c214.21,819.21) 214.21,760 ; 214.21,760 ccw(c214.21,700.79) 172.34,742.66 cw(c214.21,700.79) 214.21,760
PD7: P7.14 U3.88 | length 1103.1
  Top Layer w10: P7.14@49.64,661.1 cw(c87.3,653.39) 77.35,690.52 ; P7.14@55,660 105,710 261.72,710 U3.88@611.3,1059.58 ; P7.14@56.1,654.64 ccw(c48.39,692.3) 85.52,682.35 ; 79.8,684.8 cw(c55,709.6) 55,674.53 ccw(c55,709.6) 79.8,684.8 ; 79.8,684.8 ccw(c104.6,660) 69.53,660 cw(c104.6,660) 79.8,684.8 ; 96.87,701.87 cw(c55,743.74) 55,684.53 ccw(c55,743.74) 96.87,701.87 ; 96.87,701.87 ccw(c138.74,660) 79.53,660 cw(c138.74,660) 96.87,701.87
PD8: P7.44 U3.55 | length 1388.4
  Top Layer w10: P7.44@49.64,2161.1 cw(c87.3,2153.39) 77.35,2190.52 ; P7.44@55,2145 P7.44@55,2160 105,2210 185,2210 280,2115 280,2033.95 U3.55@722.65,1591.29 ; P7.44@56.1,2154.64 ccw(c48.39,2192.3) 85.52,2182.35 ; 79.8,2184.8 cw(c55,2209.6) 55,2174.53 ccw(c55,2209.6) 79.8,2184.8 ; 79.8,2184.8 ccw(c104.6,2160) 69.53,2160 cw(c104.6,2160) 79.8,2184.8 ; 96.87,2201.87 cw(c55,2243.74) 55,2184.53 ccw(c55,2243.74) 96.87,2201.87 ; 96.87,2201.87 ccw(c138.74,2160) 79.53,2160 cw(c138.74,2160) 96.87,2201.87
PD9: P7.43 U3.56 | length 894.6
  Top Layer w10: P7.43@155,2160 190,2160 ; U3.56@708.74,1577.38 255,2031.11 255,2095 190,2160 ; 190,2160 cw(c190,2172.71) 178.06,2168.37 ccw(c190,2172.71) 190,2160 ; 190,2160 ccw(c190,2147.29) 178.06,2151.63 cw(c190,2147.29) 190,2160
PD10: P7.42 U3.57 | length 1299.4
  Top Layer w10: P7.42@49.64,2061.1 cw(c87.3,2053.39) 77.35,2090.52 ; P7.42@55,2055 P7.42@55,2060 100,2105 205,2105 230,2080 230,2028.27 U3.57@694.81,1563.45 ; P7.42@56.1,2054.64 ccw(c48.39,2092.3) 85.52,2082.35 ; 79.8,2084.8 cw(c55,2109.6) 55,2074.53 ccw(c55,2109.6) 79.8,2084.8 ; 79.8,2084.8 ccw(c104.6,2060) 69.53,2060 cw(c104.6,2060) 79.8,2084.8 ; 96.87,2101.87 cw(c55,2143.74) 55,2084.53 ccw(c55,2143.74) 96.87,2101.87 ; 96.87,2101.87 ccw(c138.74,2060) 79.53,2060 cw(c138.74,2060) 96.87,2101.87
PD11: P7.41 U3.58 | length 737.3
  Top Layer w10: P7.41@155,2060 170.44,2060 U3.58@680.9,1549.54
PD12: P7.40 U3.59 | length 1210.5
  Top Layer w10: P7.40@49.64,1961.1 cw(c87.3,1953.39) 77.35,1990.52 ; P7.40@55,1960 105,2010 192.59,2010 U3.59@666.97,1535.62 ; P7.40@56.1,1954.64 ccw(c48.39,1992.3) 85.52,1982.35 ; 79.8,1984.8 cw(c55,2009.6) 55,1974.53 ccw(c55,2009.6) 79.8,1984.8 ; 79.8,1984.8 ccw(c104.6,1960) 69.53,1960 cw(c104.6,1960) 79.8,1984.8 ; 96.87,2001.87 cw(c55,2043.74) 55,1984.53 ccw(c55,2043.74) 96.87,2001.87 ; 96.87,2001.87 ccw(c138.74,1960) 79.53,1960 cw(c138.74,1960) 96.87,2001.87
PD13: P7.39 U3.60 | length 827.7
  Top Layer w10: P7.39@155,1960 214.76,1960 U3.60@653.06,1521.7 ; P7.39@165.27,1949.73 cw(c190.07,1924.93) 190.07,1960 cw(c190.07,1995.07) P7.39@165.27,1970.27 ; P7.39@172.34,1942.66 cw(c214.21,1900.79) 214.21,1960 cw(c214.21,2019.21) P7.39@172.34,1977.34
PD14: P7.38 U3.61 | length 1152.8
  Top Layer w10: P7.38@49.64,1861.1 cw(c87.3,1853.39) 77.35,1890.52 ; P7.38@55,1860 105,1910 236.91,1910 U3.61@639.14,1507.78 ; P7.38@56.1,1854.64 ccw(c48.39,1892.3) 85.52,1882.35 ; 79.8,1884.8 cw(c55,1909.6) 55,1874.53 ccw(c55,1909.6) 79.8,1884.8 ; 79.8,1884.8 ccw(c104.6,1860) 69.53,1860 cw(c104.6,1860) 79.8,1884.8 ; 96.87,1901.87 cw(c55,1943.74) 55,1884.53 ccw(c55,1943.74) 96.87,1901.87 ; 96.87,1901.87 ccw(c138.74,1860) 79.53,1860 cw(c138.74,1860) 96.87,1901.87
PD15: P7.37 U3.62 | length 918.1
  Top Layer w10: P7.37@155,1860 259.08,1860 U3.62@625.22,1493.86 ; 190.07,1860 cw(c190.07,1895.07) 165.27,1870.27 ccw(c190.07,1895.07) 190.07,1860 ; 190.07,1860 ccw(c190.07,1824.93) 165.27,1849.73 cw(c190.07,1824.93) 190.07,1860 ; 214.21,1860 cw(c214.21,1919.21) 172.34,1877.34 ccw(c214.21,1919.21) 214.21,1860 ; 214.21,1860 ccw(c214.21,1800.79) 172.34,1842.66 cw(c214.21,1800.79) 214.21,1860
PE0: P7.6 U3.97 | length 1411.2
  Top Layer w10: P7.6@49.64,261.1 cw(c87.3,253.39) 77.35,290.52 ; P7.6@55,260 105,310 230,310 477.09,557.09 477.09,674.81 U3.97@736.57,934.3 ; P7.6@56.1,254.64 ccw(c48.39,292.3) 85.52,282.35 ; 79.8,284.8 cw(c55,309.6) 55,274.53 ccw(c55,309.6) 79.8,284.8 ; 79.8,284.8 ccw(c104.6,260) 69.53,260 cw(c104.6,260) 79.8,284.8 ; 96.87,301.87 cw(c55,343.74) 55,284.53 ccw(c55,343.74) 96.87,301.87 ; 96.87,301.87 ccw(c138.74,260) 79.53,260 cw(c138.74,260) 96.87,301.87
PE1: P7.5 U3.98 | length 1247.2
  Top Layer w10: P7.5@155,260 230,260 494.17,524.17 494.17,664.07 U3.98@750.49,920.38 ; 190.07,260 cw(c190.07,295.07) 165.27,270.27 ccw(c190.07,295.07) 190.07,260 ; 190.07,260 ccw(c190.07,224.93) 165.27,249.73 cw(c190.07,224.93) 190.07,260 ; 214.21,260 cw(c214.21,319.21) 172.34,277.34 ccw(c214.21,319.21) 214.21,260 ; 214.21,260 ccw(c214.21,200.79) 172.34,242.66 cw(c214.21,200.79) 214.21,260
PE2: P6.9 U3.1 | length 1658.6
  Top Layer w10: U3.1@864.63,892.54 917.91,839.26 917.91,487.09 995,410 1665,410 P6.9@1715,460 ; 1684.48,437.65 cw(c1721.61,427.7) P6.9@1713.9,465.36 ; 1692.65,429.48 ccw(c1682.7,466.61) P6.9@1720.36,458.9 ; 1673.13,418.13 cw(c1715,376.26) 1715,435.47 ccw(c1715,376.26) 1673.13,418.13 ; 1673.13,418.13 ccw(c1631.26,460) 1690.47,460 cw(c1631.26,460) 1673.13,418.13 ; 1690.2,435.2 cw(c1715,410.4) 1715,445.47 ccw(c1715,410.4) 1690.2,435.2 ; 1690.2,435.2 ccw(c1665.4,460) 1700.47,460 cw(c1665.4,460) 1690.2,435.2
PE3: P6.10 U3.2 | length 1438.7
  Top Layer w10: U3.2@878.54,906.46 935,850 935,515 1020,430 1470,430 1500,460 P6.10@1615,460 ; 1555.79,460 cw(c1555.79,400.79) 1597.66,442.66 ccw(c1555.79,400.79) 1555.79,460 ; 1555.79,460 ccw(c1555.79,519.21) 1597.66,477.34 cw(c1555.79,519.21) 1555.79,460 ; 1579.93,460 cw(c1579.93,424.93) 1604.73,449.73 ccw(c1579.93,424.93) 1579.93,460 ; 1579.93,460 ccw(c1579.93,495.07) 1604.73,470.27 cw(c1579.93,495.07) 1579.93,460
PE4: P6.11 U3.3 | length 1630.4
  Top Layer w10: U3.3@892.46,920.38 955,857.85 955,540 1045,450 1430,450 1490,510 1665,510 P6.11@1715,560 ; 1684.48,537.65 cw(c1721.61,527.7) P6.11@1713.9,565.36 ; 1692.65,529.48 ccw(c1682.7,566.61) P6.11@1720.36,558.9 ; 1673.13,518.13 cw(c1715,476.26) 1715,535.47 ccw(c1715,476.26) 1673.13,518.13 ; 1673.13,518.13 ccw(c1631.26,560) 1690.47,560 cw(c1631.26,560) 1673.13,518.13 ; 1690.2,535.2 cw(c1715,510.4) 1715,545.47 ccw(c1715,510.4) 1690.2,535.2 ; 1690.2,535.2 ccw(c1665.4,560) 1700.47,560 cw(c1665.4,560) 1690.2,535.2
PE5: P6.12 U3.4 | length 1394.7
  Top Layer w10: U3.4@906.38,934.3 975,865.68 975,585 1085,475 1395,475 1480,560 P6.12@1615,560 ; 1555.79,560 cw(c1555.79,500.79) 1597.66,542.66 ccw(c1555.79,500.79) 1555.79,560 ; 1555.79,560 ccw(c1555.79,619.21) 1597.66,577.34 cw(c1555.79,619.21) 1555.79,560 ; 1579.93,560 cw(c1579.93,524.93) 1604.73,549.73 ccw(c1579.93,524.93) 1579.93,560 ; 1579.93,560 ccw(c1579.93,595.07) 1604.73,570.27 cw(c1579.93,595.07) 1579.93,560
PE6: P6.13 U3.5 | length 1566.5
  Top Layer w10: U3.5@920.3,948.22 995,873.52 995,630 1120,505 1370,505 1475,610 1665,610 P6.13@1715,660 ; 1684.48,637.65 cw(c1721.61,627.7) P6.13@1713.9,665.36 ; 1692.65,629.48 ccw(c1682.7,666.61) P6.13@1720.36,658.9 ; 1673.13,618.13 cw(c1715,576.26) 1715,635.47 ccw(c1715,576.26) 1673.13,618.13 ; 1673.13,618.13 ccw(c1631.26,660) 1690.47,660 cw(c1631.26,660) 1673.13,618.13 ; 1690.2,635.2 cw(c1715,610.4) 1715,645.47 ccw(c1715,610.4) 1690.2,635.2 ; 1690.2,635.2 ccw(c1665.4,660) 1700.47,660 cw(c1665.4,660) 1690.2,635.2
PE7: P6.38 U3.38 | length 879.3
  Top Layer w10.02: U3.38@1031.66,1479.94 1189.6,1637.88 1192.3,1637.88 1374.32,1819.9 1574.9,1819.9 ; P6.38@1590.49,1859.24 cw(c1537.2,1857.6) 1574.9,1819.9 ; P6.38@1600.51,1859.55 cw(c1569,1858.58) 1591.29,1836.29 cw(c1613.58,1814) P6.38@1614.55,1845.51 ; P6.38@1614.24,1835.49 ccw(c1612.6,1782.2) 1574.9,1819.9 ; P6.38@1615,1860 1574.9,1819.9
PE8: P6.39 U3.39 | length 1271.2
  Top Layer w10.02: U3.39@1017.73,1493.86 1178.78,1654.9 1185.25,1654.9 1367.27,1836.92 1496.92,1836.92 1570,1910 1665,1910 P6.39@1715,1960 ; 1684.53,1937.77 cw(c1721.59,1927.84) P6.39@1713.89,1965.43 ; 1692.77,1929.53 ccw(c1682.84,1966.59) P6.39@1720.43,1958.89 ; 1673.15,1918.15 cw(c1715,1876.29) 1715,1935.48 ccw(c1715,1876.29) 1673.15,1918.15 ; 1673.15,1918.15 ccw(c1631.29,1960) 1690.48,1960 cw(c1631.29,1960) 1673.15,1918.15 ; 1690.25,1935.25 cw(c1715,1910.5) 1715,1945.5 ccw(c1715,1910.5) 1690.25,1935.25 ; 1690.25,1935.25 ccw(c1665.5,1960) 1700.5,1960 cw(c1665.5,1960) 1690.25,1935.25
PE9: P6.40 U3.40 | length 1023.2
  Top Layer w10.02: U3.40@1003.82,1507.78 1167.96,1671.92 1178.2,1671.92 1360.22,1853.94 1458.94,1853.94 1565,1960 ; P6.40@1615,1960 1565,1960 ; 1565,1960 cw(c1565,1921.28) 1595.62,1944.99 ccw(c1565,1921.28) 1565,1960 ; 1565,1960 ccw(c1565,1998.72) 1595.62,1975.01 cw(c1565,1998.72) 1565,1960 ; 1585.44,1960 cw(c1585.44,1937.1) 1603.54,1951.12 ccw(c1585.44,1937.1) 1585.44,1960 ; 1585.44,1960 ccw(c1585.44,1982.9) 1603.54,1968.88 cw(c1585.44,1982.9) 1585.44,1960
PE10: P6.41 U3.41 | length 1328.9
  Top Layer w10.02: U3.41@989.9,1521.7 1157.14,1688.94 1171.15,1688.94 1353.17,1870.96 1425.96,1870.96 1565,2010 1665,2010 P6.41@1715,2060 ; 1684.53,2037.77 cw(c1721.59,2027.84) P6.41@1713.89,2065.43 ; 1692.77,2029.53 ccw(c1682.84,2066.59) P6.41@1720.43,2058.89 ; 1673.15,2018.15 cw(c1715,1976.29) 1715,2035.48 ccw(c1715,1976.29) 1673.15,2018.15 ; 1673.15,2018.15 ccw(c1631.29,2060) 1690.48,2060 cw(c1631.29,2060) 1673.15,2018.15 ; 1690.25,2035.25 cw(c1715,2010.5) 1715,2045.5 ccw(c1715,2010.5) 1690.25,2035.25 ; 1690.25,2035.25 ccw(c1665.5,2060) 1700.5,2060 cw(c1665.5,2060) 1690.25,2035.25
PE11: P6.42 U3.42 | length 1081
  Top Layer w10.02: U3.42@975.98,1535.62 1146.33,1705.96 1164.1,1705.96 1346.12,1887.98 1392.98,1887.98 1565,2060 ; P6.42@1615,2060 1565,2060 ; 1565,2060 cw(c1565,2021.28) 1595.62,2044.99 ccw(c1565,2021.28) 1565,2060 ; 1565,2060 ccw(c1565,2098.72) 1595.62,2075.01 cw(c1565,2098.72) 1565,2060 ; 1585.44,2060 cw(c1585.44,2037.1) 1603.54,2051.12 ccw(c1585.44,2037.1) 1585.44,2060 ; 1585.44,2060 ccw(c1585.44,2082.9) 1603.54,2068.88 cw(c1585.44,2082.9) 1585.44,2060
PE12: P6.43 U3.43 | length 1386.7
  Top Layer w10.02: U3.43@962.06,1549.54 1135.5,1722.98 1157.05,1722.98 1339.07,1905 1345,1905 1550,2110 1665,2110 P6.43@1715,2160 ; 1684.53,2137.77 cw(c1721.59,2127.84) P6.43@1713.89,2165.43 ; 1692.77,2129.53 ccw(c1682.84,2166.59) P6.43@1720.43,2158.89 ; 1673.15,2118.15 cw(c1715,2076.29) 1715,2135.48 ccw(c1715,2076.29) 1673.15,2118.15 ; 1673.15,2118.15 ccw(c1631.29,2160) 1690.48,2160 cw(c1631.29,2160) 1673.15,2118.15 ; 1690.25,2135.25 cw(c1715,2110.5) 1715,2145.5 ccw(c1715,2110.5) 1690.25,2135.25 ; 1690.25,2135.25 ccw(c1665.5,2160) 1700.5,2160 cw(c1665.5,2160) 1690.25,2135.25
PE13: P6.44 U3.44 | length 1029.8
  Top Layer w10.02: U3.44@948.14,1563.45 1124.69,1740 1150,1740 1570,2160 ; P6.44@1615,2160 1570,2160 ; 1570,2160 cw(c1570,2130.96) 1594.4,2146.71 ccw(c1570,2130.96) 1570,2160 ; 1570,2160 ccw(c1570,2189.04) 1594.4,2173.29 cw(c1570,2189.04) 1570,2160
PE14: P6.45 U3.45 | length 1494.7
  Top Layer w10.02: U3.45@934.22,1577.38 1116.84,1760 1145.93,1760 1405,2019.07 1405,2105 1510,2210 1665,2210 P6.45@1715,2260 ; 1684.53,2237.77 cw(c1721.59,2227.84) P6.45@1713.89,2265.43 ; 1692.77,2229.53 ccw(c1682.84,2266.59) P6.45@1720.43,2258.89 ; 1673.15,2218.15 cw(c1715,2176.29) 1715,2235.48 ccw(c1715,2176.29) 1673.15,2218.15 ; 1673.15,2218.15 ccw(c1631.29,2260) 1690.48,2260 cw(c1631.29,2260) 1673.15,2218.15 ; 1690.25,2235.25 cw(c1715,2210.5) 1715,2245.5 ccw(c1715,2210.5) 1690.25,2235.25 ; 1690.25,2235.25 ccw(c1665.5,2260) 1700.5,2260 cw(c1665.5,2260) 1690.25,2235.25
PE15: P6.46 U3.46 | length 1321.4
  Top Layer w10.02: U3.46@920.3,1591.29 1110,1780.99 1142.85,1780.99 1365,2003.14 1365,2095 1530,2260 P6.46@1615,2260 ; 1555.81,2260 cw(c1555.81,2200.81) 1597.66,2242.66 ccw(c1555.81,2200.81) 1555.81,2260 ; 1555.81,2260 ccw(c1555.81,2319.19) 1597.66,2277.34 cw(c1555.81,2319.19) 1555.81,2260 ; 1580,2260 cw(c1580,2225) 1604.75,2249.75 ccw(c1580,2225) 1580,2260 ; 1580,2260 ccw(c1580,2295) 1604.75,2270.25 cw(c1580,2295) 1580,2260
TYPE_C: C9.2 P1.1 U1.A4 U1.A9 U1.B4 U1.B9
VBAT: C4.2 D1.3 U3.6 | length 1142.2
  Top Layer w10.02: U3.6@934.22,962.14 1017.05,879.31 v1(1017.05,865)
  Bottom Layer w10.02: C4.2@1015,787 1017.05,789.05 v1(1017.05,865) ; C4.2@1007.94,798.06 ccw(c985.94,820.06) 1017.05,820.06 cw(c985.94,820.06) C4.2@1007.94,798.06 ; 1017.05,810.18 ccw(c1034.18,810.18) 1022.06,798.06 cw(c1034.18,810.18) 1017.05,810.18
  Bottom Layer w15: v1(1017.05,865) 1145,992.95 1145,1355 1327.75,1537.75 D1.3@1382.4,1537.75
VCCA: C11.1 P6.23 R17.1 U3.22 | length 1485.8
  Top Layer w10: U3.22@1156.94,1184.86 1201.79,1140 v1(1255,1140) ; v1(1425,1127.5) 1547.5,1127.5 1560,1115 1670,1115 P6.23@1715,1160 ; 1684.48,1137.65 cw(c1721.61,1127.7) P6.23@1713.9,1165.36 ; 1692.65,1129.48 ccw(c1682.7,1166.61) P6.23@1720.36,1158.9 ; 1673.13,1118.13 cw(c1715,1076.26) 1715,1135.47 ccw(c1715,1076.26) 1673.13,1118.13 ; 1673.13,1118.13 ccw(c1631.26,1160) 1690.47,1160 cw(c1631.26,1160) 1673.13,1118.13 ; 1690.2,1135.2 cw(c1715,1110.4) 1715,1145.47 ccw(c1715,1110.4) 1690.2,1135.2 ; 1690.2,1135.2 ccw(c1665.4,1160) 1700.47,1160 cw(c1665.4,1160) 1690.2,1135.2
  Bottom Layer w10: v1(1255,1140) 1300,1140 C11.1@1310,1150 1360,1150 1375,1165 1424.5,1165 R17.1@1425.5,1164 1425.5,1130.5 1425,1130 v1(1425,1127.5) ; 1287.75,1144.31 cw(c1292.81,1135.55) C11.1@1301.46,1140.8 ; 1334.14,1150 cw(c1334.14,1174.14) 1317.07,1157.07 ccw(c1334.14,1174.14) 1334.14,1150 ; 1334.14,1150 ccw(c1334.14,1125.86) 1317.07,1142.93 cw(c1334.14,1125.86) 1334.14,1150 ; v1@1422.51,1128.94 ccw(c1410.24,1136.02) 1423.93,1139.69 ; v1@1422.51,1128.94 ccw(c1410.24,1136.02) 1423.93,1139.69 ; v1@1422.51,1128.94 ccw(c1410.24,1136.02) 1423.93,1139.69 ; v1@1425.5,1133.82 cw(c1455.68,1133.82) 1434.34,1155.16 ccw(c1455.68,1133.82) v1@1425.5,1133.82 ; v1@1425.5,1133.82 ccw(c1395.32,1133.82) 1416.66,1155.16 cw(c1395.32,1133.82) v1@1425.5,1133.82 ; 1426.4,1137.19 ccw(c1436.91,1134.38) v1@1427.49,1128.94 ; 1426.4,1137.19 ccw(c1436.91,1134.38) v1@1427.49,1128.94 ; 1426.4,1137.19 ccw(c1436.91,1134.38) v1@1427.49,1128.94 ; 1271.37,1140 ccw(c1271.37,1184.63) 1302.93,1153.07 cw(c1271.37,1184.63) 1271.37,1140 ; C11.1@1295.51,1140 ccw(c1295.51,1160.49) 1310,1146 cw(c1295.51,1160.49) C11.1@1295.51,1140 ; 1391.41,1165 cw(c1391.41,1131.41) 1415.16,1155.16 ccw(c1391.41,1131.41) 1391.41,1165 ; 1396.24,1165 ccw(c1396.24,1191.76) 1415.16,1172.84 cw(c1396.24,1191.76) 1396.24,1165 ; v1@1422.97,1129.53 ccw(c1416.85,1135.65) 1425.5,1135.65 cw(c1416.85,1135.65) v1@1422.97,1129.53
VREF+: C12.2 P6.24 R16.1 U3.21 | length 1107.4
  Top Layer w10: U3.21@1143.01,1170.93 1193.95,1120 1280,1120 C12.2@1311,1151 ; C12.2@1318,1160 C12.2@1310,1152 1362,1152 1376,1166 R16.1@1425.5,1166 1425.5,1190.5 ; P6.24@1615,1160 1565,1160 ; 1334.14,1152 cw(c1334.14,1176.14) 1317.07,1159.07 ccw(c1334.14,1176.14) 1334.14,1152 ; 1334.14,1152 ccw(c1334.14,1127.86) 1317.07,1144.93 cw(c1334.14,1127.86) 1334.14,1152 ; 1393.82,1166 cw(c1393.82,1135.82) 1415.16,1157.16 ccw(c1393.82,1135.82) 1393.82,1166 ; 1393.82,1166 ccw(c1393.82,1196.18) 1415.16,1174.84 cw(c1393.82,1196.18) 1393.82,1166 ; 1425.5,1190.5 cw(c1407.74,1190.5) 1418.16,1176.12 ccw(c1407.74,1190.5) 1425.5,1190.5 ; 1425.5,1190.5 ccw(c1443.26,1190.5) 1432.84,1176.12 cw(c1443.26,1190.5) 1425.5,1190.5 ; 1425.5,1190.5 1435,1200 1525,1200 1565,1160 ; 1565,1160 cw(c1565,1121.31) 1595.6,1144.99 ccw(c1565,1121.31) 1565,1160 ; 1565,1160 ccw(c1565,1198.69) 1595.6,1175.01 cw(c1565,1198.69) 1565,1160 ; 1585.39,1160 cw(c1585.39,1137.08) 1603.51,1151.11 ccw(c1585.39,1137.08) 1585.39,1160 ; 1585.39,1160 ccw(c1585.39,1182.92) 1603.51,1168.89 cw(c1585.39,1182.92) 1585.39,1160 ; 1289.51,1129.51 cw(c1310,1109.03) 1310,1138 ccw(c1310,1109.03) 1289.51,1129.51 ; 1294.34,1134.34 ccw(c1280.69,1148) 1300,1148 cw(c1280.69,1148) 1294.34,1134.34
VREF-: C12.1 P6.21 R15.1 U3.20 | length 1361
  Top Layer w10: U3.20@1129.1,1157.02 1186.11,1100 1300,1100 C12.1@1310,1090 1311,1091 1370.5,1091 ; 1271.37,1100 cw(c1271.37,1055.37) C12.1@1302.93,1086.93 ; C12.1@1295.51,1100 cw(c1295.51,1079.51) C12.1@1310,1094 ; R15.1@1424.5,1090 R15.1@1425.5,1091 1370.5,1091 ; 1684.48,1037.65 cw(c1721.61,1027.7) P6.21@1713.9,1065.36 ; 1692.65,1029.48 ccw(c1682.7,1066.61) P6.21@1720.36,1058.9 ; P6.21@1715,1060 1665,1010 1395,1010 1370.5,1034.5 1370.5,1091 ; 1393.82,1091 cw(c1393.82,1060.82) 1415.16,1082.16 ccw(c1393.82,1060.82) 1393.82,1091 ; 1393.82,1091 ccw(c1393.82,1121.18) 1415.16,1099.84 cw(c1393.82,1121.18) 1393.82,1091 ; 1673.13,1018.13 cw(c1715,976.26) 1715,1035.47 ccw(c1715,976.26) 1673.13,1018.13 ; 1673.13,1018.13 ccw(c1631.26,1060) 1690.47,1060 cw(c1631.26,1060) 1673.13,1018.13 ; 1690.2,1035.2 cw(c1715,1010.4) 1715,1045.47 ccw(c1715,1010.4) 1690.2,1035.2 ; 1690.2,1035.2 ccw(c1665.4,1060) 1700.47,1060 cw(c1665.4,1060) 1690.2,1035.2 ; C12.1@1317.07,1082.93 cw(c1336.56,1063.44) 1336.56,1091 ccw(c1336.56,1063.44) C12.1@1317.07,1082.93 ; C12.1@1317.07,1097.07 ccw(c1331.73,1111.73) 1331.73,1091 cw(c1331.73,1111.73) C12.1@1317.07,1097.07
VSSA: C11.2 P6.22 R18.1 U3.19 | length 1074.4
  Top Layer w10: U3.19@1115.17,1143.09 1178.27,1080 v1(1255,1080) ; v1(1415,1045) 1550,1045 1565,1060 ; P6.22@1615,1060 1565,1060 ; 1565,1060 cw(c1565,1021.31) 1595.6,1044.99 ccw(c1565,1021.31) 1565,1060 ; 1565,1060 ccw(c1565,1098.69) 1595.6,1075.01 cw(c1565,1098.69) 1565,1060 ; 1585.39,1060 cw(c1585.39,1037.08) 1603.51,1051.11 ccw(c1585.39,1037.08) 1585.39,1060 ; 1585.39,1060 ccw(c1585.39,1082.92) 1603.51,1068.89 cw(c1585.39,1082.92) 1585.39,1060
  Bottom Layer w10: v1(1255,1080) 1302,1080 C11.2@1310,1088 1342,1088 1385,1045 v1(1415,1045) 1425.5,1055.5 R18.1@1425.5,1089 R18.1@1424.5,1088 ; 1334.14,1088 cw(c1334.14,1112.14) 1317.07,1095.07 ccw(c1334.14,1112.14) 1334.14,1088 ; 1334.14,1088 ccw(c1334.14,1063.86) 1317.07,1080.93 cw(c1334.14,1063.86) 1334.14,1088 ; 1425.5,1058.82 cw(c1455.68,1058.82) 1434.34,1080.16 ccw(c1455.68,1058.82) 1425.5,1058.82 ; 1425.5,1058.82 ccw(c1395.32,1058.82) 1416.66,1080.16 cw(c1395.32,1058.82) 1425.5,1058.82 ; 1276.2,1080 ccw(c1276.2,1117.8) 1302.93,1091.07 cw(c1276.2,1117.8) 1276.2,1080 ; C11.2@1295.51,1080 cw(c1295.51,1069.51) 1302.93,1076.93 ccw(c1295.51,1069.51) C11.2@1295.51,1080
pads on no net: U1. U1.A8 U1.B8
copper on no net:
  other v2: 1230,1945.94
  other v3: 1230,2241.22

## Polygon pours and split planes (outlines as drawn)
GND on Bottom Layer "BOT Layer-VSS" (solid, remove dead copper, pour order 2): 0,2660.63 1771.65,2660.63 1771.65,0 0,0
GND on Top Layer "top Layer-VSS" (solid, remove dead copper, pour order 4): 0,0 1771.65,0 1771.65,2660.63 0,2660.63

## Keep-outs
Keep-Out Layer:
  the board outline again, w5

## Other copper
Top Layer:
  rectangle net TYPE_C: 780,2265 800,2390
  rectangle net TYPE_C: 700,2265 990,2285
  rectangle net TYPE_C: 970,2265 990,2390
  rectangle net TYPE_C: 700,2120 735,2285
  rectangle net NetR100_2: 1030,2520 1145,2590
  rectangle net NetC8_2: 750,1950 1035,1990
  rectangle net NetC8_2: 745,1935 810,2005
  rectangle net NetC8_2: 980,2120 1080,2165
  rectangle net NetC8_2: 990,1960 1010,2165
  rectangle net NetP1_2: 930,2035 955,2160
  rectangle net NetP1_2: 825,2125 955,2165
  region net 3.3V: 840,955 1130,1245 1130,1285 1110,1285 1095,1275 1065,1250 830,1015 830,1005 810,985 810,980 835,955
Bottom Layer:
  rectangle net NetR100_2: 1030,2360 1080,2590
  rectangle net NetR100_2: 690,2360 740,2590
  rectangle net NetR100_2: 690,2520 1075,2590

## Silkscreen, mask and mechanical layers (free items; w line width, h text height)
Top Overlay:
  lines w10: 5,205 205,205 ; 1565,410 1765,410
  text "PB12" at 215,2345 h30
  text "PB13" at 350,2345 h30
  text "PB11" at 1330,2345 h30
  text "PB10" at 1450,2345 h30
  text "PE15" at 1330,2246 h30
  text "PE14" at 1450,2245.53 h30
  text "PB14" at 215,2245 h30
  text "PB15" at 350,2245 h30
  text "PE13" at 1330,2147 h30
  text "PE12" at 1450,2146.06 h30
  text "PD8" at 215,2145 h30
  text "PD9" at 350,2145 h30
  text "PE11" at 1330,2048 h30
  text "PE10" at 1450,2046.58 h30
  text "PD10" at 215,2045 h30
  text "PD11" at 350,2045 h30
  text "PE9" at 1330,1949 h30
  text "PE8" at 1450,1947.11 h30
  text "PD12" at 215,1945 h30
  text "PD13" at 350,1945 h30
  text "3.3V" at 602.05,1852.09 h30
  text "PE7" at 1330,1850 h30
  text "PB2" at 1450,1847.63 h30
  text "PD14" at 215,1845 h30
  text "PD15" at 350,1845.01 h30
  text "PB1" at 1330,1751 h30
  text "PB0" at 1450,1748.16 h30
  text "PC6" at 215,1745 h30
  text "PC7" at 350,1745.01 h30
  text "PC5" at 1330,1652 h30
  text "PC4" at 1450,1648.68 h30
  text "PC8" at 215,1645 h30
  text "PC9" at 350,1645 h30
  text "PA7" at 1330,1553 h30
  text "PA6" at 1450,1549.21 h30
  text "PA8" at 215,1545 h30
  text "PA9" at 350,1545 h30
  text "PA5" at 1330,1454 h30
  text "PA4" at 1450,1449.74 h30
  text "PA10" at 215,1445 h30
  text "PA11" at 350,1445 h30
  text "PA2" at 1465,1395 h25 r315
  text "PA3" at 1390,1390 h25 r315
  text "PA13" at 335,1355 h30
  text "PA12" at 215,1345 h30
  text "PA0" at 1480,1300 h25 r315
  text "PA1" at 1405,1295 h25 r315
  text "PA15" at 335,1255 h30
  text "PA14" at 215,1245 h30
  text "VREF+" at 1340,1210 h25
  text "VCCA" at 1470,1210 h25
  text "PC10" at 215,1145 h30
  text "PC11" at 350,1145 h30
  text "PC12" at 215,1045 h30
  text "PD0" at 350,1045 h30
  text "VSSA" at 1410,980 h25 r45
  text "VREF-" at 1480,975 h25 r45
  text "PD1" at 215,945 h30
  text "PD2" at 350,945 h30
  text "PC2" at 1480,900 h25 r45
  text "PC3" at 1400,890 h25 r45
  text "PD3" at 215,845 h30
  text "PD4" at 350,845 h30
  text "PC1" at 1365,845 h30
  text "PC0" at 1470,845 h30
  text "PD5" at 215,745 h30
  text "PD6" at 350,745 h30
  text "PC15" at 1330,745 h30
  text "PC14" at 1450,745 h30
  text "GND" at 519.98,670 h30
  text "GND" at 820,670 h30
  text "PD7" at 215,645 h30
  text "PB3" at 350,645 h30
  text "PC13" at 1330,645 h30
  text "PE6" at 1450,645 h30
  text "BOOT0" at 460,565 h30
  text "BOOT1" at 820,565 h30
  text "PB4" at 215,545 h30
  text "PB5" at 350,545 h30
  text "PE5" at 1330,545 h30
  text "PE4" at 1450,545 h30
  text "3.3V" at 494.99,465 h30
  text "3.3V" at 820,465 h30
  text "PB6" at 215,445 h30
  text "PB7" at 350,445 h30
  text "PE3" at 1435,435 h30 r45
  text "PE2" at 1500,425 h30 r45
  text "PB8" at 215,345 h30
  text "PB9" at 350,345 h30
  text "PE0" at 215,245 h30
  text "PE1" at 350,245 h30
  text "GND" at 1435,245 h30
  text "KEY1_NRST" at 295,175 h30
  text "KEY2_PA0" at 1240,175 h30
  text "3.3V" at 690,135 h30 r90
  text "DIO" at 790,135 h30 r90
  text "GND" at 890,135 h30 r90
  text "CLK" at 990,135 h30 r90
  text "RST" at 1090,135 h30 r90
  text "3.3V" at 255,120 h30 r90
Bottom Overlay:
  lines w10: 0,10 205,10 205,205 0,205 0,10 ; 1565,10 1770,10 1770,410 1565,410 1565,10
  text "GND" at 1545,235 h30
  text "3.3V" at 335,80 h30

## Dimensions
0,0 to 1771.65,0 on Mechanical 1
0,2660.63 to 0,0 on Mechanical 1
